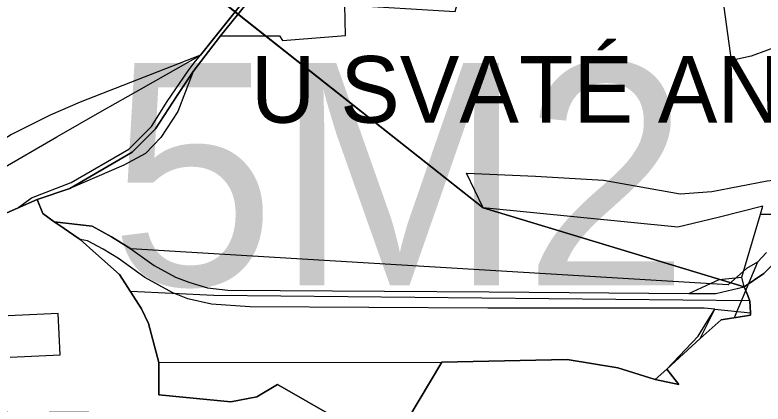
# Model space of a CAD drawing. Extents: x -706771 to -698463, y -971709 to -967107.
# Drawn here: x -705977 to -705305, y -969665 to -969315 of the extents above; entities that cross this region are included whole.
import ezdxf

# ---------------------------------------------------------------- set-up
doc = ezdxf.new("R2010")
doc.units = 0
for name, color, linetype in [('_KRAJINNY CELEK', 7, 'Continuous'), ('_KRAJINNY OKRSEK', 7, 'Continuous'), ('_KRAJINNY OKRSEK_popis', 7, 'Continuous'), ('Hranice katastralnich uzemi', 7, 'Continuous'), ('Hranice řešeného území', 7, 'Continuous'), ('KN_Hranice_parcel', 7, 'Continuous'), ('Komunikace I třídy osy N', 7, 'Continuous'), ('Komunikace popis smery a sipky', 7, 'Continuous'), ('Trasy cykloturistické N', 7, 'Continuous'), ('Trasy turistické S', 7, 'Continuous'), ('Typ krajiny běžné 5L5', 7, 'Continuous'), ('Typ krajiny běžné 5M2', 7, 'Continuous'), ('Typ krajiny popis', 7, 'Continuous')]:
    doc.layers.add(name, color=color, linetype=linetype)

msp = doc.modelspace()

# ---------------------------------------------------------------- linework, layer by layer
at = {"layer": '_KRAJINNY CELEK'}
for points in [[(-706015.8, -969507.23), (-705974.37, -969488.98), (-705956.66, -969481.18), (-705951.67, -969494.05), (-705941.55, -969501.3), (-705937.34, -969504.15), (-705923.79, -969513.33), (-705918, -969517.26), (-705903.89, -969529.84), (-705882.7, -969548.73), (-705862.83, -969579.64), (-705856.81, -969592.97), (-705847.39, -969627.87), (-705847.39, -969631.7), (-705847.36, -969657.14), (-705782.79, -969663.18), (-705759.32, -969658.73), (-705740.87, -969647.85), (-705687.4, -969678.25)], [(-705623.83, -969679.01), (-705593.1, -969627.63), (-705480.64, -969625.23), (-705434.89, -969632.73), (-705401.38, -969643.36), (-705380.38, -969647.72), (-705390.94, -969633.83), (-705360.96, -969606.47), (-705342.35, -969589.48), (-705332.94, -969588.05), (-705328.86, -969587.43), (-705315.88, -969585.46), (-705315.96, -969583.15), (-705316.15, -969577.72), (-705316.33, -969572.76), (-705318.33, -969567.76), (-705321.55, -969559.75), (-705303.93, -969547.8)]]:
    msp.add_lwpolyline(points, dxfattribs=at)
at = {"layer": '_KRAJINNY OKRSEK'}
for points in [[(-706015.8, -969507.23), (-705974.37, -969488.98), (-705956.66, -969481.18), (-705951.67, -969494.05), (-705941.55, -969501.3), (-705937.34, -969504.15), (-705923.79, -969513.33), (-705918, -969517.26), (-705903.89, -969529.84), (-705882.7, -969548.73), (-705862.83, -969579.64), (-705856.81, -969592.97), (-705847.39, -969627.87), (-705847.39, -969631.7), (-705847.36, -969657.14), (-705782.79, -969663.18), (-705759.32, -969658.73), (-705740.87, -969647.85), (-705687.4, -969678.25)], [(-705623.83, -969679.01), (-705593.1, -969627.63), (-705480.64, -969625.23), (-705434.89, -969632.73), (-705401.38, -969643.36), (-705380.38, -969647.72), (-705390.94, -969633.83), (-705360.96, -969606.47), (-705342.35, -969589.48), (-705332.94, -969588.05), (-705328.86, -969587.43), (-705315.88, -969585.46), (-705315.96, -969583.15), (-705316.15, -969577.72), (-705316.33, -969572.76), (-705318.33, -969567.76), (-705321.55, -969559.75), (-705303.93, -969547.8)]]:
    msp.add_lwpolyline(points, dxfattribs=at)
at = {"layer": 'Hranice katastralnich uzemi'}
for points in [[(-706015.8, -969507.23), (-705974.37, -969488.98), (-705956.66, -969481.18), (-705927.26, -969471.43), (-705871.21, -969438.87), (-705850.52, -969417.77), (-705830.99, -969387.84), (-705816.66, -969366.26), (-705792.04, -969334.09), (-705762.72, -969297.63)], [(-705762.72, -969297.63), (-705792.04, -969334.09), (-705816.66, -969366.26), (-705830.99, -969387.84), (-705850.52, -969417.77), (-705871.21, -969438.87), (-705927.26, -969471.43), (-705956.66, -969481.18), (-705951.67, -969494.05), (-705941.55, -969501.3), (-705937.34, -969504.15), (-705923.79, -969513.33), (-705918, -969517.26), (-705903.89, -969529.84), (-705882.7, -969548.73), (-705862.83, -969579.64), (-705856.81, -969592.97), (-705847.39, -969627.87), (-705847.39, -969631.7), (-705847.36, -969657.14), (-705782.79, -969663.18), (-705759.32, -969658.73), (-705740.87, -969647.85), (-705687.4, -969678.25)], [(-705623.83, -969679.01), (-705593.1, -969627.63), (-705480.64, -969625.23), (-705434.89, -969632.73), (-705401.38, -969643.36), (-705380.38, -969647.72), (-705390.94, -969633.83), (-705360.96, -969606.47), (-705342.35, -969589.48), (-705332.94, -969588.05), (-705328.86, -969587.43), (-705315.88, -969585.46), (-705315.96, -969583.15), (-705316.15, -969577.72), (-705316.33, -969572.76), (-705318.33, -969567.76), (-705321.55, -969559.75), (-705303.93, -969547.8)]]:
    msp.add_lwpolyline(points, dxfattribs=at)
at = {"layer": 'Hranice řešeného území'}
for points in [[(-705687.4, -969678.25), (-705740.87, -969647.85), (-705759.32, -969658.73), (-705782.79, -969663.18), (-705847.36, -969657.14), (-705847.39, -969631.7), (-705847.39, -969627.87), (-705856.81, -969592.97), (-705862.83, -969579.64), (-705882.7, -969548.73), (-705903.89, -969529.84), (-705918, -969517.26), (-705923.79, -969513.33), (-705937.34, -969504.15), (-705941.55, -969501.3), (-705951.67, -969494.05), (-705956.66, -969481.18), (-705974.37, -969488.98), (-706015.8, -969507.23)], [(-705303.93, -969547.8), (-705321.55, -969559.75), (-705318.33, -969567.76), (-705316.33, -969572.76), (-705316.15, -969577.72), (-705315.96, -969583.15), (-705315.88, -969585.46), (-705328.86, -969587.43), (-705332.94, -969588.05), (-705342.35, -969589.48), (-705360.96, -969606.47), (-705390.94, -969633.83), (-705380.38, -969647.72), (-705401.38, -969643.36), (-705434.89, -969632.73), (-705480.64, -969625.23), (-705593.1, -969627.63), (-705623.83, -969679.01)]]:
    msp.add_lwpolyline(points, dxfattribs=at)
at = {"layer": 'KN_Hranice_parcel'}
for p, q in [((-705792.04, -969334.09), (-705816.66, -969366.26)), ((-705792.04, -969334.09), (-705816.66, -969366.26)), ((-705927.26, -969471.43), (-705956.66, -969481.18)), ((-705927.26, -969471.43), (-705956.66, -969481.18)), ((-705974.37, -969488.98), (-705956.66, -969481.18)), ((-706015.8, -969507.23), (-705974.37, -969488.98)), ((-705323.55, -969551.13), (-705306.99, -969494.53)), ((-705306.99, -969494.53), (-705287.07, -969494.42)), ((-705941.55, -969501.3), (-705937.34, -969504.15)), ((-705321.55, -969559.75), (-705323.55, -969551.13)), ((-705360.96, -969606.47), (-705347.81, -969580.06)), ((-705347.81, -969580.06), (-705315.96, -969583.15)), ((-705342.35, -969589.48), (-705332.94, -969588.05)), ((-705332.94, -969588.05), (-705328.86, -969587.43)), ((-705360.96, -969606.47), (-705342.35, -969589.48)), ((-705390.94, -969633.83), (-705360.96, -969606.47)), ((-705847.39, -969627.87), (-705593.1, -969627.63)), ((-705847.39, -969627.87), (-705847.39, -969631.7)), ((-705847.39, -969631.7), (-705847.36, -969657.14)), ((-705401.38, -969643.36), (-705390.94, -969633.83)), ((-705759.32, -969658.73), (-705740.87, -969647.85))]:
    msp.add_line(p, q, dxfattribs=at)
for points in [[(-705809.98, -969351.48), (-705794.8, -969332.22), (-705767.94, -969298.65), (-705733.32, -969255.22), (-705713.22, -969229.33), (-705683.33, -969183.03), (-705660.23, -969146.79), (-705622.84, -969087.57), (-705590.72, -969037.61), (-705584.96, -969005.09), (-705563.94, -968967.94), (-705542.95, -968920.8), (-705520.26, -968868.98), (-705506.35, -968836.09)], [(-705792.04, -969334.09), (-705739.09, -969334.17), (-705736.36, -969338.21), (-705679.72, -969333.82), (-705680.18, -969306.3), (-705581.16, -969312.31), (-705571.72, -969276.68), (-705459.56, -969288.12), (-705450.44, -969273.44), (-705451.28, -969257.48), (-705458.15, -969238.34), (-705470.53, -969239.75), (-705486.24, -969169.72), (-705462.03, -969133.36), (-705434.48, -969038.08)], [(-705220.02, -969328.86), (-705286.02, -969341.49), (-705315.21, -969352.35), (-705332.99, -969356.13), (-705348.28, -969244.83), (-705334.75, -969238.45), (-705237.87, -969213.37), (-705227.97, -969214.21), (-705220.02, -969328.86)], [(-705709.35, -969234.13), (-705762.72, -969297.63), (-705792.04, -969334.09)], [(-705709.35, -969234.13), (-705762.72, -969297.63), (-705792.04, -969334.09)], [(-706100.18, -969517.53), (-706067.68, -969498.62), (-705993.02, -969456.21), (-705938.93, -969424.87), (-705898.22, -969401.63), (-705863.11, -969381.74), (-705809.98, -969351.48)], [(-705974.37, -969488.98), (-705961.67, -969479.94), (-705926.27, -969466.08), (-705874.43, -969436.16), (-705853.96, -969415.52), (-705839.77, -969393.12), (-705821.02, -969365.55), (-705815.61, -969358.41), (-705809.98, -969351.48)], [(-705816.66, -969366.26), (-705830.99, -969387.84), (-705850.52, -969417.77), (-705871.21, -969438.87), (-705927.26, -969471.43)], [(-705816.66, -969366.26), (-705830.36, -969402.28), (-705845.61, -969425.56), (-705859.43, -969439.87), (-705878.77, -969450.42), (-705927.26, -969471.43)], [(-705816.66, -969366.26), (-705830.99, -969387.84), (-705850.52, -969417.77), (-705871.21, -969438.87), (-705927.26, -969471.43)], [(-705306.99, -969494.53), (-705304.78, -969487.17), (-705344.77, -969497.55), (-705381.02, -969506.16), (-705555.92, -969488.68), (-705571.11, -969457.65), (-705508.88, -969460.25), (-705448.04, -969463.78), (-705378.92, -969476.22), (-705350.46, -969474.08), (-705301, -969464.53), (-705263.98, -969460.56), (-705236.86, -969463.64), (-705228.44, -969463.64), (-705159.81, -969455.3), (-705149.38, -969456.29)], [(-705956.66, -969481.18), (-705951.67, -969494.05), (-705941.55, -969501.3)], [(-705321.55, -969559.75), (-705303.93, -969547.8), (-705261.6, -969505.35), (-705244.73, -969495.49), (-705207.86, -969481.43)], [(-705941.55, -969501.3), (-705907.31, -969505.32), (-705889.91, -969515.01), (-705872.58, -969525.62), (-705851.69, -969540.66), (-705832.54, -969551.1), (-705820.44, -969555.79), (-705803.69, -969560.7), (-705785.53, -969562.92), (-705550.52, -969564.48), (-705371.24, -969565.74)], [(-705937.34, -969504.15), (-705923.79, -969513.33), (-705918, -969517.26)], [(-705918, -969517.26), (-705903.89, -969529.84), (-705882.7, -969548.73)], [(-705347.81, -969580.06), (-705357.51, -969579.12), (-705551.76, -969579.02), (-705765.75, -969577.73), (-705800.04, -969575.55), (-705821.47, -969570.79), (-705834.84, -969565.35), (-705860.02, -969551.46), (-705883.64, -969534.42), (-705897.3, -969526.11), (-705911.46, -969518.58), (-705918, -969517.26)], [(-705882.7, -969548.73), (-705862.83, -969579.64), (-705856.81, -969592.97), (-705847.39, -969627.87)], [(-705371.24, -969565.74), (-705344.04, -969553.19), (-705323.55, -969551.13)], [(-705371.24, -969565.74), (-705346.96, -969565.91), (-705321.55, -969559.75)], [(-705315.96, -969583.15), (-705316.15, -969577.72), (-705316.33, -969572.76), (-705318.33, -969567.76), (-705321.55, -969559.75)], [(-705390.94, -969633.83), (-705362.98, -969604.25), (-705347.81, -969580.06)], [(-705328.86, -969587.43), (-705315.88, -969585.46), (-705315.96, -969583.15)], [(-705740.87, -969647.85), (-705687.4, -969678.25), (-705623.83, -969679.01), (-705593.1, -969627.63)], [(-705593.1, -969627.63), (-705480.64, -969625.23), (-705434.89, -969632.73), (-705401.38, -969643.36)], [(-705401.38, -969643.36), (-705380.38, -969647.72), (-705390.94, -969633.83)], [(-705847.36, -969657.14), (-705782.79, -969663.18), (-705759.32, -969658.73)]]:
    msp.add_lwpolyline(points, dxfattribs=at)
at = {"layer": 'Komunikace I třídy osy N'}
msp.add_lwpolyline([(-705316.49, -969572.37), (-705797.95, -969567.59), (-705872.85, -969564.05)], dxfattribs=at)
at = {"layer": 'Komunikace popis smery a sipky'}
for p, q in [((-705937.78, -969583.91), (-705982.73, -969586.01)), ((-705936.05, -969621.15), (-705937.78, -969583.91)), ((-705981, -969623.25), (-705936.05, -969621.15))]:
    msp.add_line(p, q, dxfattribs=at)
at = {"layer": 'Trasy cykloturistické N'}
for points in [[(-705872.58, -969525.62), (-705889.91, -969515.01), (-705907.31, -969505.32), (-705941.55, -969501.3)], [(-705309.48, -969537.66), (-705319.44, -969543.28), (-705335.79, -969557.96), (-705872.58, -969525.62)], [(-705301.45, -969528.96), (-705309.48, -969537.66), (-705330.48, -969587.68)]]:
    msp.add_lwpolyline(points, dxfattribs=at)
at = {"layer": 'Trasy turistické S'}
msp.add_lwpolyline([(-705483.86, -968807.35), (-705500.29, -968822.06), (-705505.41, -968833.86), (-705520.26, -968868.98), (-705542.95, -968920.8), (-705563.94, -968967.94), (-705584.96, -969005.09), (-705590.72, -969037.61), (-705660.23, -969146.79), (-705683.33, -969183.03), (-705713.22, -969229.33), (-705767.94, -969298.65), (-705809.98, -969351.48), (-705917.95, -969393.87), (-705945.07, -969405.56), (-705979.64, -969422.9), (-706049.74, -969467.57), (-706084.53, -969519.6)], dxfattribs=at)
at = {"layer": 'Typ krajiny běžné 5L5'}
for points in [[(-705803.57, -969292.66), (-705555.92, -969488.68), (-705321.55, -969559.75)], [(-705321.55, -969559.75), (-705303.93, -969547.8), (-705261.6, -969505.35), (-705244.73, -969495.49), (-705207.86, -969481.43), (-705159.71, -969459.28), (-705135.95, -969474.88), (-705132.21, -969479.18), (-705131.57, -969479.91), (-705123.86, -969488.76), (-705120.45, -969492.67), (-705147.24, -969509.82), (-705155.06, -969518.56), (-705168.76, -969532.72), (-705186.05, -969544.86)]]:
    msp.add_lwpolyline(points, dxfattribs=at)
at = {"layer": 'Typ krajiny běžné 5M2'}
for p, q in [((-705555.92, -969488.68), (-705803.57, -969292.66)), ((-705321.55, -969559.75), (-705555.92, -969488.68))]:
    msp.add_line(p, q, dxfattribs=at)
for points in [[(-706015.8, -969507.23), (-705974.37, -969488.98), (-705956.66, -969481.18), (-705951.67, -969494.05), (-705941.55, -969501.3), (-705937.34, -969504.15), (-705923.79, -969513.33), (-705918, -969517.26), (-705903.89, -969529.84), (-705882.7, -969548.73), (-705862.83, -969579.64), (-705856.81, -969592.97), (-705847.39, -969627.87), (-705847.39, -969631.7), (-705847.36, -969657.14), (-705782.79, -969663.18), (-705759.32, -969658.73), (-705740.87, -969647.85), (-705687.4, -969678.25)], [(-705623.83, -969679.01), (-705593.1, -969627.63), (-705480.64, -969625.23), (-705434.89, -969632.73), (-705401.38, -969643.36), (-705380.38, -969647.72), (-705390.94, -969633.83), (-705360.96, -969606.47), (-705342.35, -969589.48), (-705332.94, -969588.05), (-705328.86, -969587.43), (-705315.88, -969585.46), (-705315.96, -969583.15), (-705316.15, -969577.72), (-705316.33, -969572.76), (-705318.33, -969567.76), (-705321.55, -969559.75)]]:
    msp.add_lwpolyline(points, dxfattribs=at)

# ---------------------------------------------------------------- texts
at = {"layer": '_KRAJINNY OKRSEK_popis'}
msp.add_text('U SVATÉ ANNY', height=60, dxfattribs=at).set_placement((-705764.67, -969412.25))
at = {"layer": 'Komunikace popis smery a sipky'}
msp.add_text('NOVÝ BOR', height=75, dxfattribs=at).set_placement((-706411.37, -969747.15))
at = {"layer": 'Typ krajiny popis'}
msp.add_text('5M2', height=200, dxfattribs=at).set_placement((-705891.48, -969558.59))

doc.saveas('drawing.dxf')
